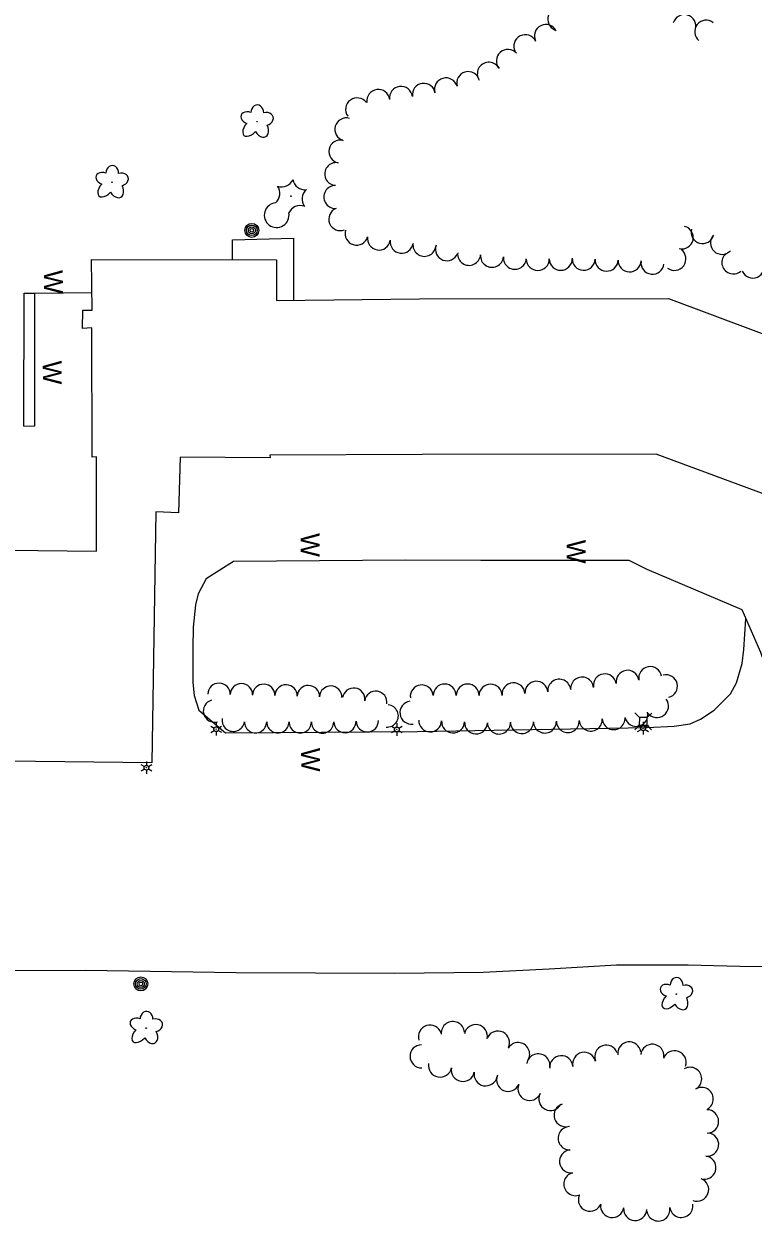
# Model space of a CAD drawing. Extents: x 588843 to 2552415, y 180129 to 269402.
# Drawn here: x 594294.4 to 594526.1, y 183985.7 to 184366.4 of the extents above; entities that cross this region are included whole.
import ezdxf

# ---------------------------------------------------------------- set-up
doc = ezdxf.new("R2010")
doc.units = 0
for name, color, linetype in [('Default', 7, 'Continuous'), ('E_AREA', 7, 'Continuous'), ('E_BLD', 7, 'Continuous'), ('E_DWY', 7, 'Continuous'), ('E_LAND_TreeLine_P', 7, 'Continuous'), ('E_LAND_Vegetation', 7, 'Continuous'), ('E_LTG', 7, 'Continuous'), ('E_MISCPROP', 7, 'Continuous'), ('E_UTL_AG_Bold', 7, 'Continuous'), ('E_WAL', 7, 'Continuous'), ('E_WAL_Text', 7, 'Continuous')]:
    doc.layers.add(name, color=color, linetype=linetype)

# ---------------------------------------------------------------- blocks, each defined once
blk = doc.blocks.new('DTRE')
at = {"layer": 'Default'}
blk.add_circle((-0.18, 0), 0.183, dxfattribs=at)
for centre, major_axis, ratio in [((-1.87, 5.32), (1.36, -4.98), 0.782863), ((4.06, 2.74), (-5.27, -2.93), 0.691916), ((-5.87, 0.15), (4.93, -0.12), 0.832022), ((-2.49, -5.24), (1.8, 4.86), 0.716896), ((3.54, -3.71), (-5.01, 4.58), 0.560249)]:
    blk.add_ellipse(centre, major_axis=major_axis, ratio=ratio, start_param=1.570796, end_param=4.712389, dxfattribs=at)
blk = doc.blocks.new('POLE')
at = {"layer": 'Default'}
for radius in [4.46, 3.35, 2.23, 1.12]:
    blk.add_circle((0, 0), radius, dxfattribs=at)
blk = doc.blocks.new('CTRE')
at = {"layer": 'Default'}
blk.add_circle((0, 0), 0.223, dxfattribs=at)
for centre, start, end in [((-11.97, 8.96), 280.2067, 5.97162), ((1.81, 14.92), 220.21132, 305.97623), ((13.83, 5.89), 160.21133, 245.97624), ((-13.83, -5.9), 340.21132, 65.97623), ((-1.81, -14.93), 40.21133, 125.97624), ((12.03, -9.04), 185.92721, 100.25111)]:
    blk.add_arc(centre, 7.87, start, end, dxfattribs=at)
blk = doc.blocks.new('W_11')
at = {"layer": 'E_WAL_Text'}
blk.add_text('W', height=12, dxfattribs=at).set_placement((-4.46, -6))
blk = doc.blocks.new('LPOL')
at = {"layer": 'Default'}
for p, q in [((-4, 0), (-1.5, 0)), ((-0.75, 1.3), (-2, 3.46)), ((0.75, 1.3), (2, 3.46)), ((1.5, 0), (4, 0)), ((-2, -3.46), (-0.75, -1.3)), ((2, -3.46), (0.75, -1.3))]:
    blk.add_line(p, q, dxfattribs=at)
for radius in [1.5, 1.5, 1.5, 0.125]:
    blk.add_circle((0, 0), radius, dxfattribs=at)
blk = doc.blocks.new('W_36')
at = {"layer": 'E_WAL_Text'}
blk.add_text('W', height=12, dxfattribs=at).set_placement((-4.46, -6))
blk = doc.blocks.new('PED')
at = {"layer": 'Default'}
for p, q in [((-2.5, 2.5), (-5.33, 5.33)), ((2.5, 2.5), (5.33, 5.33)), ((-2.5, -2.5), (-5.33, -5.33)), ((2.5, -2.5), (5.33, -5.33))]:
    blk.add_line(p, q, dxfattribs=at)
blk.add_lwpolyline([(-2.5, -2.5), (2.5, -2.5), (2.5, 2.5), (-2.5, 2.5)], close=True, dxfattribs=at)

msp = doc.modelspace()

# ---------------------------------------------------------------- linework, layer by layer
at = {"layer": 'E_AREA'}
msp.add_lwpolyline([(594360.63, 184291.43), (594360.65, 184297.82), (594380.05, 184298.27), (594380.07, 184278.52)], dxfattribs=at)
at = {"layer": 'E_BLD'}
for points in [[(594270.63, 184199.23), (594317.46, 184198.7), (594317.39, 184228.71), (594316.09, 184228.67), (594315.93, 184269.77), (594313.02, 184269.58), (594313.09, 184275.4), (594316.09, 184275.37), (594315.84, 184291.51), (594374.68, 184291.4), (594374.63, 184278.46), (594420.1, 184278.97)], [(594420.1, 184278.97), (594499.27, 184279.14), (594614.5, 184236), (594658.94, 184183.75), (594623.49, 184153.78), (594588.64, 184195.04), (594495.27, 184229.58), (594420.94, 184229.53)], [(594420.94, 184229.53), (594372.5, 184229.3), (594372.61, 184228.46), (594344.06, 184228.6), (594343.45, 184210.98), (594336.3, 184211.25), (594335.03, 184131.39), (594270.25, 184132.15)]]:
    msp.add_lwpolyline(points, dxfattribs=at)
at = {"layer": 'E_DWY'}
for points in [[(594360.93, 184195.49), (594352.32, 184189.92), (594349.7, 184185.15), (594348.85, 184181.69), (594348.19, 184174.57), (594348.05, 184167.91), (594348.02, 184157.01), (594348.47, 184152.89), (594349.99, 184148.19)], [(594558.17, 184078.65), (594546.81, 184112.17), (594536.6, 184143.25), (594528.62, 184166.56), (594522.59, 184180.08), (594492.4, 184192.87), (594486.76, 184195.76)], [(594492.48, 184142.64), (594501.08, 184143.1), (594506.16, 184143.87), (594509.41, 184145.31), (594513.74, 184148.21), (594518.92, 184153.35), (594520.88, 184156.87), (594522.6, 184163.07), (594523.15, 184167.51), (594523.84, 184177.28)], [(594412.28, 184064.38), (594361.83, 184064.64), (594313.89, 184065.35), (594284.17, 184065.27), (594254.79, 184064.68), (594227.3, 184064.25), (594212.84, 184064.31), (594207.31, 184064.55), (594204.59, 184065.98), (594203.01, 184068.21), (594201.69, 184072.37), (594200.76, 184079.96), (594200.46, 184088.67), (594201.99, 184103.8), (594202.93, 184107.56), (594204.58, 184111.45), (594206.18, 184114.05), (594212.19, 184117.12), (594218.87, 184121.03), (594233.09, 184124.11), (594240.73, 184126.39), (594242.24, 184127.51), (594243.25, 184128.81), (594244.03, 184138.73)], [(594565.32, 184065.53), (594563.11, 184064.35), (594561.41, 184064.71), (594549.41, 184065.91), (594538.28, 184066.43), (594521.92, 184066.67), (594505.53, 184067.12), (594482.72, 184067.1), (594461.32, 184065.85), (594440.36, 184064.72), (594412.28, 184064.38)]]:
    msp.add_lwpolyline(points, dxfattribs=at)
at = {"layer": 'E_LAND_TreeLine_P'}
for centre, radius, start, end in [((594464.52, 184367.9), 3.65, 68.8433, 248.8433), ((594504.25, 184365.76), 3.65, 344.0302, 164.0302), ((594511.19, 184363.97), 3.65, 51.1966, 231.1966), ((594460.26, 184362.59), 3.65, 25.7498, 205.7498), ((594453.72, 184359.36), 3.65, 26.5549, 206.5549), ((594448.16, 184354.67), 3.65, 41.6323, 221.6323), ((594442.11, 184350.6), 3.65, 33.3462, 213.3462), ((594428.52, 184345.62), 3.65, 15.9287, 195.9287), ((594435.54, 184347.62), 3.65, 15.9287, 195.9287), ((594406.99, 184341.95), 3.65, 7.6464, 187.6464), ((594414.22, 184342.92), 3.65, 7.6464, 187.6464), ((594421.45, 184343.89), 3.65, 7.6464, 187.6464), ((594400.25, 184339.27), 3.65, 35.9357, 215.9357), ((594396.83, 184332.9), 3.65, 74.0253, 254.0253), ((594394.94, 184325.85), 3.65, 78.1658, 258.1658), ((594393.62, 184318.68), 3.65, 82.1933, 262.1933), ((594393.35, 184311.4), 3.65, 90.028, 270.028), ((594394.9, 184304.35), 3.65, 111.7058, 291.7058), ((594400.09, 184299.75), 3.65, 163.4001, 343.4001), ((594503.47, 184298.51), 3.65, 256.4047, 76.4047), ((594510.05, 184300.23), 3.65, 164.8716, 344.8716), ((594516.23, 184296.79), 3.65, 136.6611, 316.6611), ((594407.2, 184298.16), 3.65, 170.3384, 350.3384), ((594414.42, 184297.14), 3.65, 172.2895, 352.2895), ((594421.65, 184296.16), 3.65, 172.2037, 352.2037), ((594428.78, 184294.76), 3.65, 159.3211, 339.3211), ((594435.86, 184293.3), 3.65, 175.0324, 355.0324), ((594443.13, 184292.67), 3.65, 175.0324, 355.0324), ((594450.4, 184292.04), 3.65, 175.0324, 355.0324), ((594457.68, 184291.68), 3.65, 180.3239, 0.3239), ((594464.98, 184291.72), 3.65, 180.3239, 0.3239), ((594472.27, 184291.75), 3.65, 177.782, 357.782), ((594479.57, 184291.47), 3.65, 177.782, 357.782), ((594486.86, 184291.19), 3.65, 177.782, 357.782), ((594501.13, 184291.71), 3.65, 233.5049, 53.5049), ((594519.82, 184290.58), 3.65, 130.1369, 310.1369), ((594494.12, 184290.49), 3.65, 173.5047, 353.5047), ((594526, 184289.27), 3.65, 204.0239, 24.0239), ((594493.41, 184158.38), 3.65, 10.2551, 190.2551), ((594471.77, 184155.05), 3.65, 5.3274, 185.3274), ((594479, 184156.07), 3.65, 8.9752, 188.9752), ((594486.2, 184157.21), 3.65, 8.9752, 188.9752), ((594498.42, 184155.81), 3.65, 283.6777, 103.6777), ((594356.37, 184153.21), 3.55, 358.9866, 178.9866), ((594363.47, 184153.08), 3.55, 358.9866, 178.9866), ((594370.57, 184152.9), 3.55, 358.4223, 178.4223), ((594377.67, 184152.71), 3.55, 358.4223, 178.4223), ((594384.76, 184152.51), 3.55, 358.4223, 178.4223), ((594391.86, 184152.32), 3.55, 358.4223, 178.4223), ((594399.17, 184151.68), 3.55, 351.8446, 171.8446), ((594420.8, 184152.55), 3.65, 7.1634, 187.1634), ((594428.08, 184152.84), 3.65, 359.9116, 179.9116), ((594435.38, 184152.83), 3.65, 359.9116, 179.9116), ((594442.67, 184152.82), 3.65, 359.9116, 179.9116), ((594449.96, 184153.23), 3.65, 3.8477, 183.8477), ((594457.24, 184153.72), 3.65, 3.8477, 183.8477), ((594464.51, 184154.37), 3.65, 5.3274, 185.3274), ((594354.92, 184147.93), 3.55, 105.5968, 285.5968), ((594406.2, 184150.67), 3.55, 351.8446, 171.8446), ((594417.52, 184147.38), 3.65, 97.9509, 277.9509), ((594495.58, 184149.47), 3.65, 216.8852, 36.8852), ((594409.81, 184146.35), 3.55, 264.1595, 84.1595), ((594489, 184146.66), 3.65, 193.8432, 13.8432), ((594360.9, 184144.97), 3.55, 171.6136, 351.6136), ((594367.97, 184144.51), 3.55, 179.805, 359.805), ((594375.07, 184144.48), 3.55, 179.805, 359.805), ((594382.17, 184144.46), 3.55, 179.805, 359.805), ((594389.27, 184144.43), 3.55, 179.805, 359.805), ((594396.37, 184144.57), 3.55, 181.7398, 1.7398), ((594403.47, 184144.79), 3.55, 181.7398, 1.7398), ((594423.47, 184144.89), 3.65, 177.6825, 357.6825), ((594430.76, 184144.59), 3.65, 177.6825, 357.6825), ((594438.05, 184144.3), 3.65, 177.6825, 357.6825), ((594445.35, 184144.24), 3.65, 181.2865, 1.2865), ((594452.64, 184144.4), 3.65, 181.2865, 1.2865), ((594459.94, 184144.56), 3.65, 181.2865, 1.2865), ((594467.23, 184144.73), 3.65, 181.2865, 1.2865), ((594474.52, 184145.17), 3.65, 183.6918, 3.6918), ((594481.8, 184145.64), 3.65, 183.6918, 3.6918), ((594423.43, 184044.35), 3.69, 17.5905, 197.5905), ((594430.68, 184045.48), 3.69, 4.5611, 184.5611), ((594437.97, 184044.48), 3.69, 347.8553, 167.8553), ((594445.02, 184042.43), 3.69, 334.087, 154.087), ((594420.77, 184038.08), 3.69, 90.7831, 270.7831), ((594451.42, 184038.77), 3.69, 328.0766, 148.0766), ((594479.46, 184037.94), 3.69, 19.4905, 199.4905), ((594486.76, 184039), 3.69, 7.6242, 187.6242), ((594494.09, 184038.25), 3.69, 353.7336, 173.7336), ((594457.86, 184035.19), 3.69, 350.0868, 170.0868), ((594465.16, 184034.6), 3.69, 4.0966, 184.0966), ((594472.44, 184035.68), 3.69, 12.6575, 192.6575), ((594501.14, 184036.2), 3.69, 340.2752, 160.2752), ((594426.62, 184035.14), 3.69, 169.1962, 349.1962), ((594433.87, 184033.76), 3.69, 169.1962, 349.1962), ((594441.12, 184032.37), 3.69, 169.1962, 349.1962), ((594506.1, 184030.92), 3.69, 299.9629, 119.9629), ((594448.25, 184030.6), 3.69, 156.9797, 336.9797), ((594455.05, 184027.72), 3.69, 156.9797, 336.9797), ((594461.7, 184024.53), 3.69, 152.6056, 332.6056), ((594509.78, 184024.53), 3.69, 299.9629, 119.9629), ((594466.56, 184019.38), 3.69, 107.7679, 287.7679), ((594511.47, 184017.39), 3.69, 271.0686, 91.0686), ((594467.83, 184012.03), 3.69, 91.8523, 271.8523), ((594511.5, 184010.02), 3.69, 263.2097, 83.2097), ((594468.29, 184004.67), 3.69, 97.6404, 277.6404), ((594510.63, 184002.69), 3.69, 263.2097, 83.2097), ((594469.63, 183997.46), 3.69, 112.9623, 292.9623), ((594508.31, 183995.71), 3.69, 249.3498, 69.3498), ((594474.26, 183992.49), 3.69, 159.6616, 339.6616), ((594481.33, 183990.5), 3.69, 172.044, 352.044), ((594503.29, 183990.53), 3.69, 188.9099, 8.9099), ((594488.65, 183989.55), 3.69, 176.7304, 356.7304), ((594496, 183989.39), 3.69, 188.9099, 8.9099)]:
    msp.add_arc(centre, radius, start, end, dxfattribs=at)
at = {"layer": 'E_WAL'}
for points in [[(594294.37, 184238.51), (594297.84, 184238.63), (594297.79, 184280.81), (594316, 184281.05)], [(594294.37, 184238.51), (594294.47, 184280.79), (594297.79, 184280.81)], [(594415.63, 184195.89), (594360.93, 184195.49)], [(594486.76, 184195.76), (594439.61, 184195.77), (594415.63, 184195.89)], [(594349.99, 184148.19), (594358.45, 184140.96), (594419.48, 184141.43)], [(594419.48, 184141.43), (594492.48, 184142.64)]]:
    msp.add_lwpolyline(points, dxfattribs=at)

# ---------------------------------------------------------------- block references
at = {"layer": 'E_LAND_Vegetation', "yscale": 0.5}
for name, p, xscale, rotation in [('DTRE', (594368.43, 184335.27), 0.49999999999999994, -90.03098035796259), ('DTRE', (594322.34, 184316), 0.49999999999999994, -90.03098035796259), ('CTRE', (594379.22, 184311.64), 0.49999999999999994, -90.03098035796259), ('DTRE', (594501.71, 184057.76), 0.4999999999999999, -90.21750690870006), ('DTRE', (594333.21, 184046.99), 0.5, -90.44645755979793)]:
    msp.add_blockref(name, p, dxfattribs=dict(at, xscale=xscale, rotation=rotation))
at = {"layer": 'E_LTG'}
for p, xscale, yscale, rotation in [((594355.47, 184142.13), 0.49999999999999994, 0.5000000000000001, -89.630833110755), ((594412.89, 184142.05), 0.49999999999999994, 0.5, -90.03098035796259), ((594491.16, 184142.42), 0.5000000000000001, 0.5, -90.36283032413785), ((594333.3, 184129.88), 0.49999999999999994, 0.5000000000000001, -89.630833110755)]:
    msp.add_blockref('LPOL', p, dxfattribs=dict(at, xscale=xscale, yscale=yscale, rotation=rotation))
at = {"layer": 'E_MISCPROP', "yscale": 0.5}
for p, xscale, rotation in [((594366.8, 184300.78), 0.49999999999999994, -90.03098035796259), ((594331.51, 184061.12), 0.5, -90.44645755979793)]:
    msp.add_blockref('POLE', p, dxfattribs=dict(at, xscale=xscale, rotation=rotation))
at = {"layer": 'E_UTL_AG_Bold', "xscale": 0.5000000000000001, "yscale": 0.5, "rotation": -90.36283032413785}
msp.add_blockref('PED', (594491.21, 184144.62), dxfattribs=at)
at = {"layer": 'E_WAL_Text'}
for name, p, xscale, yscale, rotation in [('W_11', (594303.73, 184285.93), 0.49999999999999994, 0.5000000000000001, -89.630833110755), ('W_11', (594303.36, 184257.11), 0.49999999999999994, 0.5000000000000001, -89.630833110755), ('W_11', (594385.32, 184202.25), 0.49999999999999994, 0.5000000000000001, -89.630833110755), ('W_36', (594469.9, 184200.17), 0.5000000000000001, 0.5, -90.36283032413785), ('W_11', (594385.46, 184133.95), 0.49999999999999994, 0.5000000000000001, -89.630833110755)]:
    msp.add_blockref(name, p, dxfattribs=dict(at, xscale=xscale, yscale=yscale, rotation=rotation))

doc.saveas('drawing.dxf')
